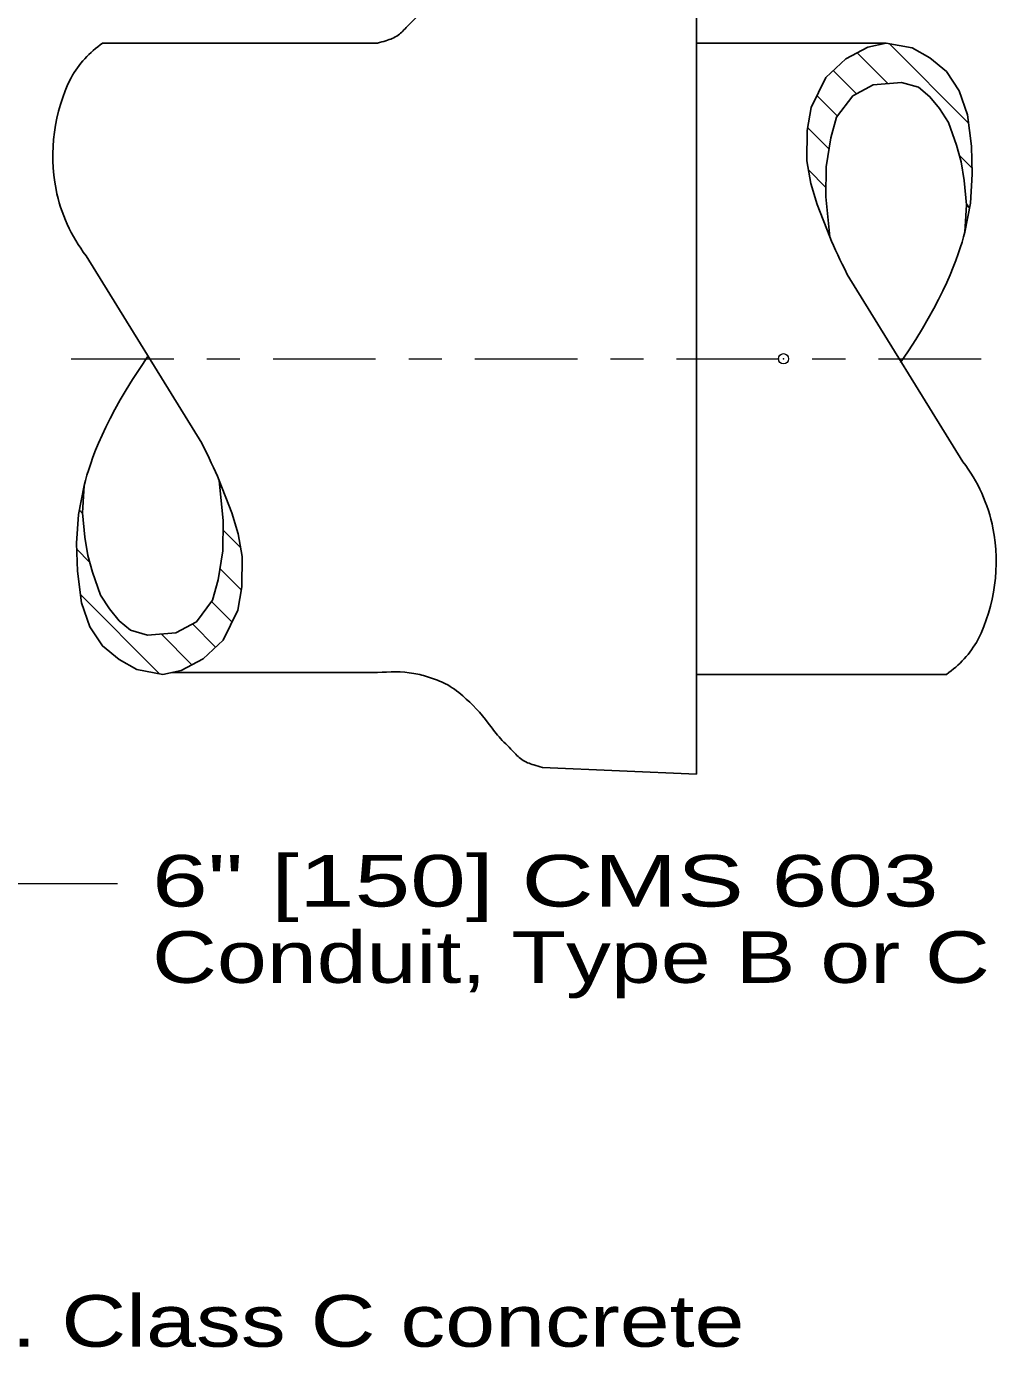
# Model space of a CAD drawing. Extents: x 1083.1 to 1117.1, y 719.4 to 741.4.
# Drawn here: x 1093.92 to 1096.862, y 723.432 to 727.471 of the extents above; entities that cross this region are included whole.
import ezdxf

# ---------------------------------------------------------------- set-up
doc = ezdxf.new("R2010")
doc.units = 0
doc.header["$LTSCALE"] = 0.062
doc.header["$PDMODE"] = 32
doc.header["$PDSIZE"] = 0.031
doc.linetypes.add('DOT_DASHED', pattern=[7.7, 5, -1.2, 0.3, -1.2])
doc.layers.add('1', color=7, linetype='Continuous', lineweight=13)

msp = doc.modelspace()

# ---------------------------------------------------------------- linework, layer by layer
at = {"layer": '1', "lineweight": 25}
for p, q in [((1095.94383, 727.77608), (1095.94383, 725.21108)), ((1094.14858, 727.42125), (1094.97975, 727.42125)), ((1095.94383, 727.42125), (1096.51725, 727.42125)), ((1096.5275, 727.41933), (1096.76617, 727.17983)), ((1096.42967, 727.39217), (1096.52258, 727.29892)), ((1096.35783, 727.33883), (1096.42808, 727.26825)), ((1096.30842, 727.263), (1096.37042, 727.20075)), ((1096.27992, 727.16625), (1096.34492, 727.10092)), ((1096.73875, 727.08167), (1096.7775, 727.043)), ((1096.28283, 727.03783), (1096.33517, 726.98525)), ((1096.76, 726.93508), (1096.76975, 726.92525)), ((1096.76017, 726.93125), (1096.76925, 726.922)), ((1096.75725, 726.88183), (1096.76083, 726.87825)), ((1096.33875, 726.85617), (1096.34542, 726.8495)), ((1096.34475, 726.84042), (1096.3465, 726.83883)), ((1094.44858, 726.21167), (1094.09908, 726.77842)), ((1096.40008, 726.72225), (1096.74958, 726.1555)), ((1094.50392, 726.0935), (1094.50217, 726.09508)), ((1094.50992, 726.07775), (1094.50325, 726.0845)), ((1094.09142, 726.05208), (1094.08783, 726.05567)), ((1094.35883, 725.5185), (1094.97975, 725.5185)), ((1095.94383, 725.51267), (1096.70008, 725.51267)), ((1095.47842, 725.231), (1095.94383, 725.21108))]:
    msp.add_line(p, q, dxfattribs=at)
at = {"layer": '1', "linetype": 'DOT_DASHED'}
msp.add_line((1094.05425, 726.467), (1096.85033, 726.467), dxfattribs=at)
at = {"layer": '1'}
for p, q in [((1094.08875, 725.99883), (1094.07892, 726.00875)), ((1094.56583, 725.89617), (1094.5135, 725.94867)), ((1094.10992, 725.85225), (1094.07125, 725.89092)), ((1094.56883, 725.76767), (1094.50375, 725.833)), ((1094.32117, 725.51458), (1094.08258, 725.75408)), ((1094.54033, 725.67092), (1094.47825, 725.73325)), ((1094.49083, 725.59508), (1094.42058, 725.66567)), ((1094.419, 725.54175), (1094.32608, 725.635))]:
    msp.add_line(p, q, dxfattribs=at)
at = {"layer": '1', "lineweight": 25}
for points in [[(1096.34692, 726.83533), (1096.30883, 726.93308), (1096.28992, 726.99692), (1096.27792, 727.06542), (1096.27833, 727.15692), (1096.29058, 727.22675), (1096.33492, 727.3175), (1096.39517, 727.374), (1096.46242, 727.40958), (1096.51725, 727.42125), (1096.59583, 727.407), (1096.64992, 727.37683), (1096.7, 727.3355), (1096.73792, 727.27758), (1096.763, 727.20458), (1096.7755, 727.10975), (1096.778, 727.02483), (1096.77225, 726.93783), (1096.7555, 726.85017)], [(1096.7555, 726.85017), (1096.76025, 726.93267), (1096.753, 727.00608), (1096.74442, 727.06217), (1096.73008, 727.11258), (1096.70575, 727.18158), (1096.67858, 727.22333), (1096.64992, 727.25925), (1096.6155, 727.288), (1096.564, 727.30233), (1096.478, 727.29525), (1096.41633, 727.26208), (1096.36775, 727.19733), (1096.3505, 727.13558), (1096.33625, 727.04783), (1096.33475, 726.95717), (1096.34692, 726.83533)], [(1094.50175, 726.09867), (1094.53983, 726.00083), (1094.55875, 725.93708), (1094.57075, 725.86858), (1094.57042, 725.77692), (1094.55808, 725.70717), (1094.51383, 725.6165), (1094.4535, 725.55992), (1094.38625, 725.52433), (1094.33142, 725.51267), (1094.25283, 725.527), (1094.19875, 725.55708), (1094.14867, 725.59842), (1094.11083, 725.65633), (1094.08575, 725.72933), (1094.07325, 725.82417), (1094.07067, 725.90917), (1094.0765, 725.99617), (1094.09325, 726.08375)], [(1094.09325, 726.08375), (1094.0885, 726.00117), (1094.09567, 725.92783), (1094.10433, 725.87183), (1094.11867, 725.82142), (1094.14292, 725.75242), (1094.17017, 725.71067), (1094.19875, 725.67467), (1094.23325, 725.646), (1094.28475, 725.63158), (1094.37067, 725.63867), (1094.43242, 725.67183), (1094.481, 725.73658), (1094.49825, 725.79842), (1094.5125, 725.88617), (1094.514, 725.97683), (1094.50175, 726.09867)]]:
    msp.add_lwpolyline(points, dxfattribs=at)
at = {"layer": '1'}
msp.add_lwpolyline([(1093.50717, 725.47867), (1093.88067, 724.88017), (1094.19367, 724.88017)], dxfattribs=at)
at = {"layer": '1', "lineweight": 25}
for centre, major_axis, start_param, end_param in [((1094.33142, 727.15775), (0, 0.32118), 0.608535, 1.0523476), ((1094.52873, 727.08079), (0, -0.53235), 4.2528342, 4.9042115), ((1094.47817, 727.07248), (0, -0.48097), 4.9073919, 5.370128), ((1096.37053, 725.86145), (0, 0.48097), 4.9073919, 5.370128), ((1096.31997, 725.85315), (0, 0.53235), 4.2528342, 4.9042115), ((1096.51727, 725.77618), (0, -0.32118), 0.608535, 1.0523476)]:
    msp.add_ellipse(centre, major_axis=major_axis, ratio=0.995779, start_param=start_param, end_param=end_param, dxfattribs=at)
for points in [[(1095.47842, 727.75617), (1095.37117, 727.74158), (1095.3125, 727.71475), (1095.266, 727.68983), (1095.21683, 727.63733), (1095.16492, 727.583), (1095.11067, 727.514), (1095.06992, 727.47175), (1095.04233, 727.4455), (1095.0055, 727.42883), (1094.97975, 727.42125)], [(1094.97975, 725.5185), (1095.08975, 725.51567), (1095.13717, 725.50333), (1095.18558, 725.48433), (1095.23792, 725.44725), (1095.31492, 725.3655), (1095.34742, 725.32367), (1095.38817, 725.28142), (1095.41583, 725.25517), (1095.45258, 725.23858), (1095.47842, 725.231)]]:
    msp.add_spline(points, degree=3, dxfattribs=at)
for points in [[(1096.40008, 726.72225), (1096.37908, 726.76392), (1096.36167, 726.8015), (1096.34692, 726.83533)], [(1096.7555, 726.85017), (1096.73583, 726.77392), (1096.69458, 726.65158), (1096.56108, 726.45525)], [(1094.09325, 726.08375), (1094.11283, 726.16), (1094.15408, 726.28242), (1094.28458, 726.4725)], [(1094.44858, 726.21167), (1094.46958, 726.17008), (1094.48708, 726.13242), (1094.50175, 726.09867)]]:
    msp.add_open_spline(points, degree=3, dxfattribs=at)
at = {"layer": '1'}
msp.add_point((1096.20725, 726.46692), dxfattribs=at)

# ---------------------------------------------------------------- texts
for s, width, p in [('6" [150] CMS 603', 1.45, (1094.29875, 724.81042)), ('Conduit, Type B or C', 1.3, (1094.29875, 724.57967)), ('4" [100] min. Class C concrete', 1.3, (1092.43583, 723.47933))]:
    msp.add_text(s, height=0.156, dxfattribs=dict(at, width=width)).set_placement(p)

doc.saveas('drawing.dxf')
